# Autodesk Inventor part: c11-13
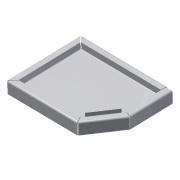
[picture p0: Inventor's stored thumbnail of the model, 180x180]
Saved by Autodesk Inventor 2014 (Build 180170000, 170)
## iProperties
Created: 2011-01
Part Number: c11-13
Material: Aluminum 6061
Document SubType Name: Sheet Metal
Designer: Thom Tremblay
Density: 2.71 g/cm^3
Sheet Metal Rule: Aluminum 3 mm
Appearance: Ceramic
Sheet Metal Width: 0.000 mm
Sheet Metal Length: 0.000 mm
Sheet Metal Area: 0.000 mm^2
Author: Thom Tremblay
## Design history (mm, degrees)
node "Face1"
  sketch "Sketch1"
    geometry: L1 (0, 0)-(240, 0); L2 (240, 0)-(240, 300); L3 (240, 300)-(0, 300); L4 (0, 300)-(0, 0); L5 (140, 300)-(240, 229.979)
    constraints: 10 end point, 2 parallel, 2 point on line, 1 horizontal, 1 perpendicular
    dimensions: "d0" = 240 distance of L3.end L2.end; "d1" = 300 distance of L2.end L1.end; "d2" = 35 deg angle of L3 L5; "d3" = 100 distance from line of L2 L5.start
node "Flange1"
node "Flange2"
node "Flange3"
body "Solid1"
face "Plate1" dims "Thickness" = 3 (derived)
sketch "Sketch2"
  geometry: L1 through (-150, 0) direction (1, 0); L2 through (0, 20) direction (0, 1); L3 (0, 40)-(-300, 40); L4 (-300, 40)-(-300, 0)
  constraints: 6 end point, 1 horizontal, 1 perpendicular, 1 vertical
face "Plate2" dims "d5" = 3 (= BendReliefWidth), "d6" = 1.5 (= BendReliefDepth), "d7" = 6 (= MinimumRemnant), "d8" = 2 (= BendRadius), "d9" = 40, "d10" = 90 deg, "d11" = 2 (= BendRadius), "d12" = 12 (= CornerReliefSize), "d13" = 1.5 (= GapSize), "d14" = 2 (= JacobiRadiusSize), "SeamGap" = 0.01, "Thickness" = 3 (derived)
bend "Bend1" dims "d5" = 3 (= BendReliefWidth), "d6" = 1.5 (= BendReliefDepth), "d7" = 6 (= MinimumRemnant), "d8" = 2 (= BendRadius), "d9" = 40, "d10" = 90 deg, "d11" = 2 (= BendRadius), "SeamGap" = 0.01, "Thickness" = 3 (derived)
feature "Corner1" dims "d9" = 40, "d10" = 90 deg, "d12" = 12 (= CornerReliefSize), "d13" = 1.5 (= GapSize), "d14" = 2 (= JacobiRadiusSize)
sketch "Sketch3"
  geometry: L1 through (-115.939, 0) direction (1, -4.87e-49); L2 through (0, 10) direction (9.72e-49, 1); L3 (0, 20)-(-231.879, 20); L4 (-231.879, 20)-(-231.879, 0)
  constraints: 6 end point, 1 horizontal, 1 perpendicular, 1 vertical
face "Plate3" dims "d15" = 3 (= BendReliefWidth), "d16" = 1.5 (= BendReliefDepth), "d17" = 6 (= MinimumRemnant), "d18" = 2 (= BendRadius), "d19" = 20, "d20" = 90 deg, "d21" = 2 (= BendRadius), "d22" = 12 (= CornerReliefSize), "d23" = 1.5 (= GapSize), "d24" = 2 (= JacobiRadiusSize), "d26" = 10, "SeamGap" = 0.01, "Thickness" = 3 (derived)
bend "Bend2" dims "d15" = 3 (= BendReliefWidth), "d16" = 1.5 (= BendReliefDepth), "d17" = 6 (= MinimumRemnant), "d18" = 2 (= BendRadius), "d19" = 20, "d20" = 90 deg, "d21" = 2 (= BendRadius), "SeamGap" = 0.01, "Thickness" = 3 (derived)
feature "Corner2" dims "d19" = 20, "d20" = 90 deg, "d22" = 12 (= CornerReliefSize), "d23" = 1.5 (= GapSize), "d24" = 2 (= JacobiRadiusSize)
sketch "Sketch4"
  geometry: L1 (-93.728, 0)-(-10, 0); L2 (-10, 0)-(-10, 15); L3 (-10, 15)-(-93.728, 15); L4 (-93.728, 15)-(-93.728, 0)
  constraints: 8 end point
face "Plate4" dims "d27" = 3 (= BendReliefWidth), "d28" = 1.5 (= BendReliefDepth), "d29" = 6 (= MinimumRemnant), "d30" = 2 (= BendRadius), "d31" = 10, "d32" = 10, "d33" = 15, "d34" = 90 deg, "d35" = 2 (= BendRadius), "d36" = 12 (= CornerReliefSize), "d37" = 1.5 (= GapSize), "d38" = 2 (= JacobiRadiusSize), "SeamGap" = 0.01, "Thickness" = 3 (derived)
bend "Bend3" dims "d27" = 3 (= BendReliefWidth), "d28" = 1.5 (= BendReliefDepth), "d29" = 6 (= MinimumRemnant), "d30" = 2 (= BendRadius), "d33" = 15, "d34" = 90 deg, "d35" = 2 (= BendRadius), "SeamGap" = 0.01, "Thickness" = 3 (derived)
feature "Corner3" dims "d33" = 15, "d34" = 90 deg, "d36" = 12 (= CornerReliefSize), "d37" = 1.5 (= GapSize), "d38" = 2 (= JacobiRadiusSize)
other parameters: "BendRadius" = 2 (derived), "BendReliefWidth" = 3 (= Thickness), "BendReliefDepth" = 1.5 (= 0.5 x Thickness), "CornerReliefSize" = 12 (= 4 x Thickness), "MinimumRemnant" = 6 (= 2 x Thickness), "TransitionRadius" = 2 (= BendRadius), "JacobiRadiusSize" = 2 (= BendRadius), "GapSize" = 1.5 (= 0.5 x Thickness), "d4" = 2 (= BendRadius)
